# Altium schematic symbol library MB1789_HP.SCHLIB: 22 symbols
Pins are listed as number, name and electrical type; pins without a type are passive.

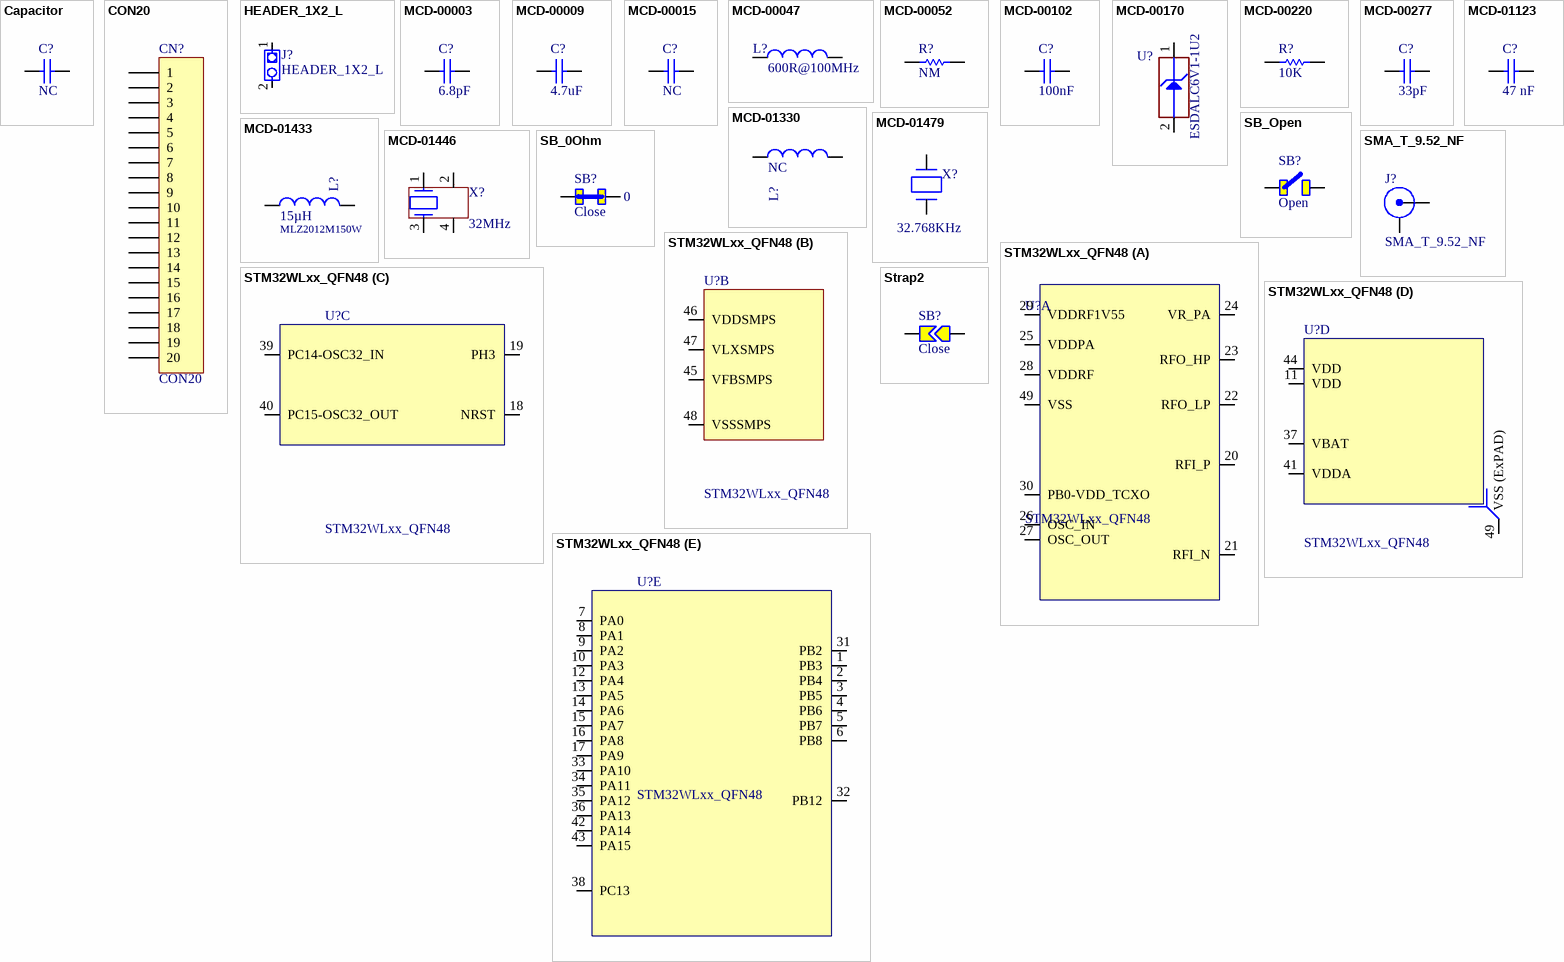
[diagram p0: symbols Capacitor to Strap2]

## Capacitor
designator C?  value NC
Condensateurs céramique multicouches MLCC - CMS 0402 3.3pF 50Volts C0G +/-0.05pF
footprint 0402
pins: 1, 2

## CON20
designator CN?
Connector
pins: 1, 2, 3, 4, 5, 6, 7, 8, 9, 10, 11, 12, 13, 14, 15, 16, 17, 18, 19, 20

## HEADER_1X2_L
designator J?
footprint Header F 1x2x2.54 TH V (1x2x2.54 Header TH V Female)
footprint Header M 1x2x2.54 TH V (1x2x2.54 Header TH V Male)
footprint Header F 1x2x2.00 TH V (1x2x2.00 Header TH V Male height=5.5mm)
footprint Header F 1x2x2.00 TH V with Jumper (1x2x2.00 Header TH V Male height=5.5mm)
footprint Header NF 1x2x2.54 TH (1x2x2.54 Header TH Not Fitted)
footprint CO_MOLEX_22-03-2021
pins: 1, 2

## MCD-00003
designator C?, comment value 6.8pF  (hidden comment: Capacitor)
Capacitor, MLCC, 6.8pF, 50V, NPO, +-0.1pF, 0402, T=0.5mm; Manufacturer_Part_Number: GRM1555C1H6R8BA01; Manufacturer: MURATA
footprint 0402
pins: 1, 2

## MCD-00009
designator C?  value 4.7uF
Capacitor, MLCC, 4.7uF, 16V, X5R, 10%, 0603, T=0.8mm; Manufacturer_Part_Number: CC0603KRX5R7BB475; Manufacturer: YAGEO
footprint CAPC1608X09N (Chip Capacitor, 2-Leads, Body 1.60x0.80x0.90mm (0603))
pins: 1, 2

## MCD-00015
designator C?  value NC
Condensateurs céramique multicouches MLCC - CMS 0402 3.3pF 50Volts C0G +/-0.05pF
footprint 0402
pins: 1, 2

## MCD-00047
designator L?  value 600R@100MHz
SMD Chip ferrite bead, 600R@100MHz +/-25%, 350mA, 500mohm DC, 0603, T=0.8mm; Manufacturer_Part_Number: BK1608HS601-T; Manufacturer: Taiyo Yuden
footprint INDC1608X95N (Chip Inductor, 2-Leads, Body 1.75x0.95x0.95mm (0603))
pins: 1, 2

## MCD-00052
designator R?, comment value NM  (hidden comment: Resistor)
Resistor,0R,0402,5%,1/16W; Internal_Part_Number: MCD-00052; Manufacturer_Part_Number: RC0402JR-070RL; Manufacturer: YAGEO; Provided_By: SUBCO; Initial_Board_Reference: MB1274
footprint R0402
pins: 1, 2

## MCD-00102
designator C?  value 100nF
Capacitor, MLCC, 100nF, 16V, X7R, 10%, 0402, T=0,5mm; Manufacturer_Part_Number: CC0402KRX7R7BB104; Manufacturer: YAGEO
footprint 0402
pins: 1, 2

## MCD-00170
designator U?  Manufacturer_Part_Number: ESDALC6V1-1U2
ESD protection 6V1; Manufacturer: STMICROELECTRONICS
footprint DIOM0603X03N (Molded Diode, 2-Leads, Body 0.60x0.30mm)
pins: 1 IO1, 2 GND

## MCD-00220
designator R?  value 10K
Resistor,10K,0603,1%,1/10W; Manufacturer_Part_Number: RC0603FR-0710KL; Manufacturer: YAGEO
footprint RESC1608X05N (Chip Resistor, 2-Leads, Body 1.60x0.80mm (0603))
pins: 1, 2

## MCD-00277
designator C?  value 33pF
Multilayer Ceramic Capacitors MLCC - SMD/SMT 0201 33pF 25volts C0G 5%; Manufacturer_Part_Number: GJM0335C1E330JB01D; Manufacturer: MURATA
footprint 0402
footprint 0201
pins: 1, 2

## MCD-01123
designator C?  value 47 nF
Capacitor, MLCC,47nF, 16V, X7R, 10%, 0402, T=0.5mm; Manufacturer_Part_Number: GCM155R71E473KA55; Manufacturer: MURATA
footprint 0402
pins: 1, 2

## MCD-01330
designator L?  value NC
Inductor, 11 nH, +-0.1nH, 270mA, 0402
footprint IND_MURATA_LQW15A (Inductor 2-Leads,Body 1.10x0.70x0.60mm(max))
footprint 0402
pins: 1, 2

## MCD-01433
designator L?  value 15µH  Manufacturer_Part_Number: MLZ2012M150W
MLZ2012 Multilayer Shielded Inductor 15µH, ±5%; Manufacturer: TDK
footprint INDC2012X13N (Chip Inductor, 2-Leads, Body 2.0x1.2x1.3 (0805))
pins: 1, 2

## MCD-01446
designator X?  value 32MHz
Crystal 32 MHz, 8pF, -+10 PPM, R=60Ω, SMD; Manufacturer_Part_Number: NX2016SA 32MHz EXS00A-CS06465; Manufacturer: NDK
footprint OSC_NDK_NX2016SA (Crystal, 4-Leads, Body 2.10x1.61x0.50mm (max), Pitch 1.35x1.05mm)
signal-integrity model Guessed Model (IC Model Details Guessed by Setup Helper)
pins: 1, 2, 3, 4

## MCD-01479
designator X?, comment value 32.768KHz  (hidden comment: XTAL_2_PINS)
Crystal 32.768kHz, 6pF, -+20PPM, R=80K, SMD; Manufacturer_Part_Number: NX2012SA 32.768KHz EXS00A-MU00527; Manufacturer: NDK
footprint OSC_NDK_NX2012SA (Crystal, 2-Leads, Body 2.05x1.20x0.55mm (Tol:-/+0.05))
pins: 1 X1, 2 X2

## SB_0Ohm
designator SB?, comment Close  value 0
Solder Bridge 0R [0402] (Populated with 0 Ohm); Manufacturer: Vishay / Dale; Manufacturer_Part_Number: RCS04020000Z0ED
footprint SB_0402 (Souder Bridge [0402])
signal-integrity model Guessed Model (IC Model Details Guessed by Setup Helper)
pins: 1, 2

## SB_Open
designator SB?, comment Open
Solder Bridge Open [0402] (Unpopulated)
footprint SB_0402 (Souder Bridge [0402])
signal-integrity model Guessed Model (IC Model Details Guessed by Setup Helper)
pins: 1, 2

## SMA_T_9.52_NF
designator J?
SMA End Launch Jack 1.0 mm Board, 50 ohm; Manufacturer: COAX CONNECTORS LTD; Manufacturer_Part_Number: 30-462-D3-1.1mm
footprint CO_SAMTEC_SMA-J-P-ST-EMI (SMA Jack CMS, Edge Mountt Receptacle 50Ohm, 5-Leads, Body 6.35x6.35x9.52mm, pitch 2.825mm)
pins: 1 X, 2 Y

## STM32WLxx_QFN48
designator U?
HQDC : Verified April, 25 2019; Manufacturer: STMicroelectronics; Manufacturer_Part_Number: STM32WLE5CC
footprint STM32WLxx_QFN48 (QFN48 7x7x0.55mm pitch 0.5mm)
part A pins: 20 RFI_P, 21 RFI_N, 22 RFO_LP, 23 RFO_HP, 24 VR_PA, 25 VDDPA, 26 OSC_IN, 27 OSC_OUT, 28 VDDRF, 29 VDDRF1V55, 30 PB0-VDD_TCXO, 49 VSS
part B pins: 45 VFBSMPS, 46 VDDSMPS, 47 VLXSMPS, 48 VSSSMPS
part C pins: 18 NRST, 19 PH3, 39 PC14-OSC32_IN, 40 PC15-OSC32_OUT
part D pins: 11 VDD, 37 VBAT, 41 VDDA, 44 VDD, 49 VSS (ExPAD)
part E pins: 1 PB3, 2 PB4, 3 PB5, 4 PB6, 5 PB7, 6 PB8, 7 PA0, 8 PA1, 9 PA2, 10 PA3, 12 PA4, 13 PA5, 14 PA6, 15 PA7, 16 PA8, 17 PA9, 31 PB2, 32 PB12, 33 PA10, 34 PA11, 35 PA12, 36 PA13, 38 PC13, 42 PA14, 43 PA15

## Strap2
designator SB?, comment Close
Solder Jumper - Close; Manufacturer: Vishay / Dale; Manufacturer_Part_Number: RCS04020000Z0ED
footprint SB
footprint GC_0402 (Grain de café format 0402)
footprint SB-LARGE
pins: 1, 2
